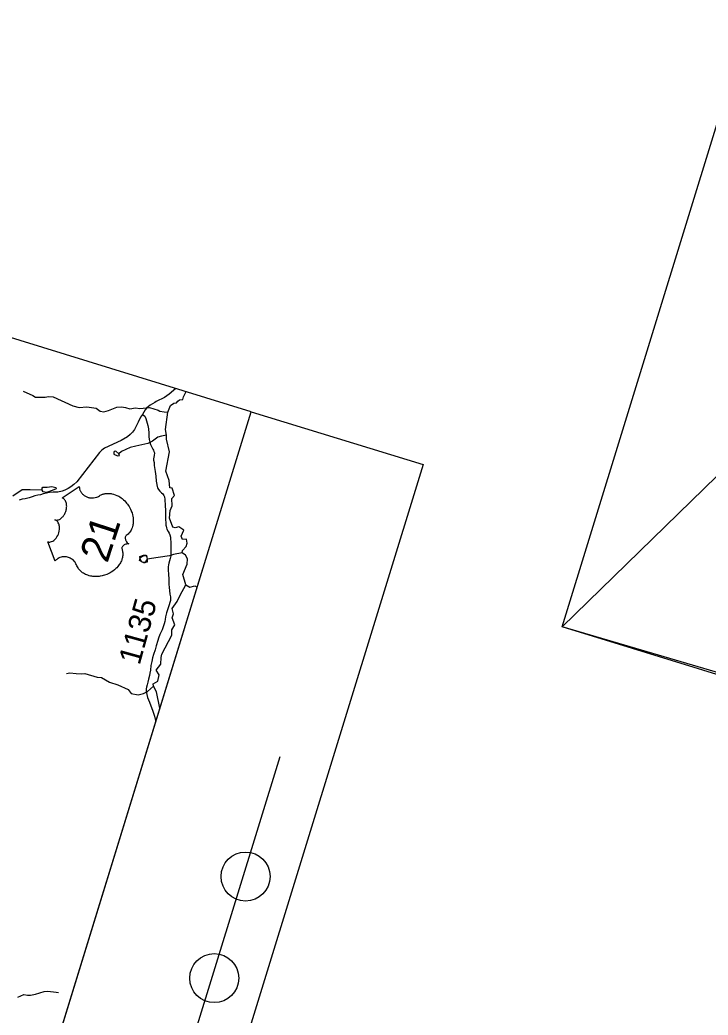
# Model space of a CAD drawing. Extents: x 1347947 to 1350662, y 1027710 to 1030532.
# Drawn here: x 1348346.4 to 1348486.3, y 1028931.2 to 1029133.4 of the extents above; entities that cross this region are included whole.
import ezdxf

# ---------------------------------------------------------------- set-up
doc = ezdxf.new("R2010")
doc.units = 0
for name, color, linetype in [('Default', 7, 'Continuous'), ('Prop Leader Line Light', 7, 'Continuous'), ('Prop Leader Line Medium', 7, 'Continuous'), ('Prop WCC CELL', 7, 'Continuous'), ('Sheet Clip Boundary CELL', 7, 'Continuous')]:
    doc.layers.add(name, color=color, linetype=linetype)

msp = doc.modelspace()

# ---------------------------------------------------------------- linework, layer by layer
at = {"layer": 'Default'}
for points in [[(1348347.12, 1029057.98), (1348349.02, 1029057.09), (1348349.61, 1029056.76), (1348351.54, 1029056.74), (1348352.24, 1029056.86), (1348353.19, 1029056.77), (1348357.15, 1029054.98), (1348358.46, 1029054.66), (1348359.99, 1029054.76), (1348361.89, 1029054.5), (1348362.71, 1029053.91), (1348363.47, 1029053.75), (1348364.41, 1029053.99), (1348366.15, 1029054.7), (1348367.05, 1029054.79), (1348367.86, 1029054.65), (1348368.73, 1029054.35), (1348369.93, 1029054.56), (1348370.79, 1029054.4), (1348372.77, 1029054.63), (1348374.51, 1029054.08), (1348374.84, 1029053.86), (1348375.76, 1029053.74), (1348376.49, 1029053.71)], [(1348378.08, 1029058.5), (1348376.76, 1029057.31), (1348375.8, 1029056.66), (1348374.14, 1029055.82), (1348373.86, 1029055.67), (1348373.35, 1029055.38), (1348372.86, 1029055.08), (1348372.24, 1029054.57), (1348371.9, 1029054.16), (1348371.32, 1029053.23)], [(1348374.86, 1028993.56), (1348374.21, 1028996.86), (1348373.6, 1028998.04), (1348373.5, 1028998.52), (1348374.42, 1028999.01), (1348374.75, 1029000.33), (1348374.14, 1029001.28), (1348375.07, 1029002.52), (1348375.11, 1029003.84), (1348375.27, 1029004.55), (1348377.29, 1029008.37), (1348377.29, 1029009.5), (1348377.91, 1029010.5), (1348377.37, 1029011.93), (1348377.66, 1029012.74), (1348377.33, 1029013.77), (1348378.37, 1029015.25), (1348378.98, 1029016.52), (1348380.12, 1029018.58), (1348379.55, 1029020.68), (1348380.44, 1029022.83), (1348380.48, 1029023.86), (1348380.05, 1029024.64), (1348379.42, 1029025.11), (1348379.49, 1029025.57), (1348380.18, 1029026.42), (1348380.4, 1029027.07), (1348380.25, 1029027.86), (1348379.47, 1029027.81), (1348379.16, 1029028.51), (1348379.73, 1029029.69), (1348378.72, 1029030.36), (1348377.96, 1029030.21), (1348377.5, 1029030.35), (1348376.8, 1029032.13), (1348376.94, 1029033.7), (1348377.34, 1029034.64), (1348377.28, 1029036.13), (1348377.83, 1029036.78), (1348377.35, 1029038.26), (1348376.91, 1029038.3), (1348376.73, 1029039.81), (1348376.08, 1029041.68), (1348376.8, 1029045.63), (1348376.18, 1029048.22), (1348376.22, 1029049.03), (1348375.99, 1029050.14), (1348376.49, 1029053.71), (1348377, 1029055.02), (1348377.69, 1029055.49), (1348378.27, 1029055.56), (1348378.48, 1029055.93), (1348378.85, 1029056.22), (1348379.53, 1029056.25), (1348379.63, 1029056.82), (1348380.18, 1029057.85)], [(1348371.32, 1029053.23), (1348370.96, 1029052.64), (1348370.43, 1029051.62), (1348370.13, 1029050.95), (1348369.68, 1029050.17), (1348369.27, 1029049.65), (1348368.85, 1029049.18), (1348368.31, 1029048.7), (1348366.99, 1029047.94), (1348363.63, 1029046.38), (1348363.08, 1029045.99), (1348362.59, 1029045.5), (1348357.97, 1029039.51), (1348357.39, 1029039.02), (1348356.77, 1029038.53), (1348356.24, 1029038.16), (1348355.96, 1029038.02), (1348355.58, 1029037.82), (1348355, 1029037.65), (1348354.15, 1029037.45), (1348353.17, 1029037.41), (1348352.46, 1029037.36), (1348351.84, 1029037.21), (1348351.18, 1029037.08), (1348350.64, 1029036.91), (1348350.1, 1029036.82), (1348349.45, 1029036.66), (1348348.9, 1029036.5), (1348348.3, 1029036.3), (1348347.5, 1029036.1), (1348346.86, 1029035.98), (1348346.29, 1029035.84)], [(1348371.32, 1029053.23), (1348371.8, 1029052.86), (1348371.98, 1029052.42), (1348372.39, 1029051), (1348372.58, 1029050.32), (1348372.63, 1029049.41), (1348372.63, 1029049.1), (1348372.65, 1029048.75), (1348372.71, 1029048.1), (1348372.83, 1029047.57), (1348372.97, 1029047.11), (1348373.15, 1029046.74), (1348373.33, 1029046.42), (1348373.46, 1029046.17), (1348373.57, 1029045.96), (1348373.65, 1029045.71), (1348373.77, 1029045.4), (1348373.73, 1029044.88), (1348373.59, 1029044.21), (1348373.6, 1029043.91), (1348373.67, 1029043.43), (1348373.71, 1029042.86), (1348373.9, 1029041.66), (1348374.06, 1029040.66), (1348374.11, 1029039.69), (1348374.18, 1029039.32), (1348374.33, 1029038.56), (1348374.39, 1029038.3), (1348374.58, 1029037.97), (1348374.85, 1029037.63), (1348375.2, 1029037.33), (1348375.45, 1029037.07), (1348375.66, 1029036.76), (1348375.77, 1029036.46), (1348375.86, 1029035.96), (1348375.92, 1029034.7), (1348376.03, 1029033.74), (1348376, 1029032.91), (1348376.03, 1029031.95), (1348376.06, 1029031.12), (1348376.08, 1029030.76), (1348376.13, 1029030.5), (1348376.18, 1029030.18), (1348376.28, 1029029.95), (1348376.53, 1029029.47), (1348376.77, 1029029.1), (1348376.86, 1029028.79), (1348376.99, 1029028.28), (1348377.02, 1029027.93), (1348377.09, 1029027.3), (1348377.09, 1029026.65), (1348377.11, 1029025.76), (1348377.09, 1029025.13), (1348377.06, 1029024.52), (1348376.93, 1029023.97), (1348376.8, 1029023.47), (1348376.68, 1029022.99), (1348376.63, 1029022.64), (1348376.58, 1029022.26), (1348376.57, 1029021.61), (1348376.59, 1029020.79), (1348376.68, 1029019.77), (1348376.66, 1029018.75), (1348376.74, 1029018.07), (1348376.83, 1029017.44), (1348376.91, 1029016.69), (1348377.01, 1029016.16), (1348377.05, 1029015.79), (1348377.01, 1029015.41), (1348376.64, 1029014.17), (1348376.42, 1029013.51), (1348376.23, 1029012.93), (1348376.03, 1029012.1), (1348375.95, 1029011.6), (1348375.84, 1029011.19), (1348375.72, 1029010.72), (1348375.3, 1029009.49), (1348374.86, 1029008.55), (1348374.61, 1029007.76), (1348374.45, 1029007.31), (1348374.1, 1029006.24), (1348373.89, 1029005.44), (1348373.56, 1029004.47), (1348373.37, 1029003.75), (1348373.22, 1029003.05), (1348373.05, 1029002.23), (1348372.93, 1029001.29), (1348372.83, 1029000.7), (1348372.73, 1029000.2), (1348372.57, 1028999.44), (1348372.42, 1028998.84), (1348372.29, 1028998.27), (1348372.12, 1028997.8), (1348372.05, 1028997.46), (1348372.05, 1028997.07), (1348372.18, 1028996.3), (1348372.37, 1028995.73), (1348372.75, 1028994.75), (1348373.42, 1028992.94), (1348373.78, 1028991.92)], [(1348376.22, 1029049.03), (1348375.22, 1029048.81), (1348374.44, 1029048.64), (1348373.37, 1029047.79), (1348372.44, 1029047.34), (1348371.21, 1029047.02), (1348369.97, 1029046.8), (1348368.81, 1029046.53), (1348367.04, 1029045.72), (1348366.53, 1029045.25)], [(1348366.53, 1029045.25), (1348365.94, 1029045.78), (1348365.6, 1029045.7), (1348365.49, 1029045.49), (1348365.5, 1029045.12), (1348366.27, 1029044.81), (1348366.63, 1029044.85), (1348366.53, 1029045.25)], [(1348366.53, 1029045.25), (1348365.94, 1029045.78), (1348365.6, 1029045.7), (1348365.49, 1029045.49), (1348365.5, 1029045.12), (1348366.27, 1029044.81), (1348366.63, 1029044.85), (1348366.53, 1029045.25)], [(1348350.95, 1029037.86), (1348348.48, 1029037.9), (1348346.88, 1029037.89), (1348344.99, 1029036.59)], [(1348350.95, 1029037.86), (1348350.93, 1029038.27), (1348351.1, 1029038.48), (1348351.98, 1029038.47), (1348352.89, 1029038.56), (1348353.69, 1029038.41), (1348353.79, 1029038.11), (1348353.01, 1029037.75), (1348351.85, 1029037.4), (1348351.16, 1029037.48), (1348350.95, 1029037.86)], [(1348379.42, 1029025.11), (1348377.63, 1029024.76), (1348376.82, 1029024.5), (1348374.54, 1029024.17), (1348372.29, 1029023.8)], [(1348372.29, 1029023.8), (1348372.3, 1029023.22), (1348371.44, 1029023.12), (1348370.74, 1029023.56), (1348370.77, 1029023.82), (1348370.95, 1029024.16), (1348371.53, 1029024.51), (1348372.12, 1029024.57), (1348372.29, 1029023.8)], [(1348371.53, 1029024.62), (1348372.1, 1029024.65), (1348372.25, 1029023.8), (1348371.84, 1029023.08), (1348371.58, 1029023.1), (1348371.23, 1029023.26), (1348370.85, 1029023.81), (1348370.76, 1029024.4), (1348371.53, 1029024.62)], [(1348380.12, 1029018.58), (1348380.97, 1029018.16), (1348381.97, 1029018.38), (1348382.43, 1029018.13)], [(1348355.92, 1029000.63), (1348356.58, 1029000.75), (1348357.84, 1029000.57), (1348358.89, 1029000.55), (1348359.59, 1029000.61), (1348362.13, 1028999.84), (1348363.03, 1028999.79), (1348364.64, 1028998.86), (1348366.33, 1028998.31), (1348368.4, 1028997.35), (1348369.03, 1028996.55), (1348370.45, 1028996.24), (1348371.53, 1028996.51), (1348372.33, 1028996.95), (1348373.6, 1028998.04)], [(1348373.78, 1028991.92), (1348373.96, 1028991.07), (1348374.02, 1028990.84)], [(1348346.01, 1028934.86), (1348347.22, 1028935.42), (1348347.98, 1028935.25), (1348348.59, 1028935.25), (1348349.59, 1028935.47), (1348351.35, 1028935.97), (1348352.13, 1028936.05), (1348353.81, 1028935.87), (1348354.24, 1028935.78)]]:
    msp.add_lwpolyline(points, dxfattribs=at)
msp.add_lwpolyline([(1348352.1, 1029027.37), (1348352.23, 1029027.33), (1348352.4, 1029027.31), (1348352.48, 1029027.31), (1348352.66, 1029027.33), (1348352.87, 1029027.39), (1348353.1, 1029027.5), (1348353.31, 1029027.64), (1348353.44, 1029027.74), (1348353.62, 1029027.91), (1348353.8, 1029028.12), (1348353.96, 1029028.36), (1348354.11, 1029028.62), (1348354.24, 1029028.91), (1348354.34, 1029029.2), (1348354.42, 1029029.53), (1348354.47, 1029029.9), (1348354.48, 1029030.08), (1348354.47, 1029030.28), (1348354.46, 1029030.47), (1348354.42, 1029030.69), (1348354.37, 1029030.87), (1348354.33, 1029031.01), (1348354.22, 1029031.23), (1348354.1, 1029031.42), (1348354.03, 1029031.5), (1348353.96, 1029031.58), (1348353.79, 1029031.7), (1348353.71, 1029031.75), (1348353.54, 1029031.82), (1348353.69, 1029031.78), (1348353.79, 1029031.77), (1348353.88, 1029031.76), (1348353.99, 1029031.77), (1348354.14, 1029031.79), (1348354.28, 1029031.83), (1348354.49, 1029031.91), (1348354.59, 1029031.97), (1348354.68, 1029032.03), (1348354.9, 1029032.2), (1348355.1, 1029032.4), (1348355.2, 1029032.51), (1348355.28, 1029032.62), (1348355.38, 1029032.76), (1348355.47, 1029032.91), (1348355.55, 1029033.06), (1348355.63, 1029033.22), (1348355.7, 1029033.39), (1348355.75, 1029033.52), (1348355.8, 1029033.69), (1348355.84, 1029033.85), (1348355.88, 1029034.02), (1348355.9, 1029034.2), (1348355.92, 1029034.36), (1348355.93, 1029034.56), (1348355.92, 1029034.75), (1348355.91, 1029034.92), (1348355.87, 1029035.14), (1348355.82, 1029035.33), (1348355.77, 1029035.47), (1348355.69, 1029035.65), (1348355.58, 1029035.83), (1348355.5, 1029035.94), (1348355.4, 1029036.03), (1348355.3, 1029036.12), (1348355.19, 1029036.19), (1348355.08, 1029036.24), (1348354.99, 1029036.27), (1348358.48, 1029038.57), (1348358.49, 1029038.49), (1348358.51, 1029038.3), (1348358.55, 1029038.14), (1348358.63, 1029037.87), (1348358.68, 1029037.75), (1348358.74, 1029037.63), (1348358.8, 1029037.52), (1348358.86, 1029037.42), (1348358.96, 1029037.29), (1348359.06, 1029037.17), (1348359.17, 1029037.04), (1348359.27, 1029036.94), (1348359.49, 1029036.77), (1348359.63, 1029036.67), (1348359.76, 1029036.6), (1348360.02, 1029036.47), (1348360.15, 1029036.42), (1348360.28, 1029036.38), (1348360.42, 1029036.34), (1348360.56, 1029036.31), (1348360.71, 1029036.29), (1348360.83, 1029036.27), (1348361, 1029036.26), (1348361.19, 1029036.26), (1348361.38, 1029036.27), (1348361.69, 1029036.33), (1348362.03, 1029036.42), (1348362.23, 1029036.5), (1348362.4, 1029036.58), (1348362.62, 1029036.72), (1348362.75, 1029036.8), (1348362.91, 1029036.88), (1348363.2, 1029037), (1348363.33, 1029037.04), (1348363.47, 1029037.08), (1348363.62, 1029037.12), (1348363.78, 1029037.15), (1348363.91, 1029037.17), (1348364.22, 1029037.19), (1348364.5, 1029037.19), (1348364.65, 1029037.18), (1348364.97, 1029037.14), (1348365.13, 1029037.11), (1348365.44, 1029037.04), (1348365.8, 1029036.92), (1348366.13, 1029036.78), (1348366.51, 1029036.59), (1348366.73, 1029036.46), (1348366.98, 1029036.29), (1348367.19, 1029036.13), (1348367.5, 1029035.87), (1348367.72, 1029035.66), (1348367.97, 1029035.4), (1348368.11, 1029035.23), (1348368.27, 1029035.03), (1348368.44, 1029034.8), (1348368.61, 1029034.53), (1348368.79, 1029034.22), (1348368.92, 1029033.97), (1348369.05, 1029033.66), (1348369.13, 1029033.47), (1348369.22, 1029033.21), (1348369.31, 1029032.86), (1348369.39, 1029032.53), (1348369.43, 1029032.25), (1348369.45, 1029032), (1348369.47, 1029031.69), (1348369.45, 1029031.19), (1348369.43, 1029031.01), (1348369.39, 1029030.81), (1348369.35, 1029030.61), (1348369.3, 1029030.43), (1348369.22, 1029030.19), (1348369.13, 1029029.95), (1348369.02, 1029029.74), (1348368.89, 1029029.52), (1348368.74, 1029029.29), (1348368.58, 1029029.1), (1348368.39, 1029028.9), (1348368.02, 1029028.6), (1348367.93, 1029028.51), (1348367.89, 1029028.45), (1348367.83, 1029028.3), (1348367.82, 1029028.15), (1348367.83, 1029027.99), (1348367.85, 1029027.89), (1348367.88, 1029027.75), (1348367.93, 1029027.64), (1348367.99, 1029027.5), (1348368.05, 1029027.4), (1348368.1, 1029027.32), (1348368.24, 1029027.16), (1348368.3, 1029027.09), (1348368.4, 1029027.02), (1348368.54, 1029026.93), (1348368.33, 1029026.95), (1348368.18, 1029026.93), (1348368.05, 1029026.9), (1348367.93, 1029026.86), (1348367.77, 1029026.8), (1348367.64, 1029026.73), (1348367.51, 1029026.64), (1348367.39, 1029026.54), (1348367.31, 1029026.46), (1348367.24, 1029026.38), (1348367.18, 1029026.28), (1348367.14, 1029026.19), (1348367.12, 1029026.11), (1348367.11, 1029026), (1348367.17, 1029025.83), (1348367.21, 1029025.66), (1348367.26, 1029025.49), (1348367.29, 1029025.29), (1348367.31, 1029025.14), (1348367.32, 1029024.97), (1348367.32, 1029024.77), (1348367.31, 1029024.57), (1348367.28, 1029024.36), (1348367.26, 1029024.18), (1348367.21, 1029023.99), (1348367.16, 1029023.82), (1348367.1, 1029023.64), (1348367.04, 1029023.48), (1348366.96, 1029023.3), (1348366.85, 1029023.08), (1348366.74, 1029022.9), (1348366.62, 1029022.71), (1348366.48, 1029022.52), (1348366.32, 1029022.32), (1348366.11, 1029022.08), (1348365.94, 1029021.91), (1348365.66, 1029021.66), (1348365.29, 1029021.38), (1348364.98, 1029021.18), (1348364.73, 1029021.04), (1348364.34, 1029020.84), (1348364.08, 1029020.73), (1348363.64, 1029020.57), (1348363.33, 1029020.48), (1348363.11, 1029020.43), (1348362.75, 1029020.36), (1348362.53, 1029020.33), (1348362.22, 1029020.3), (1348361.94, 1029020.29), (1348361.67, 1029020.29), (1348361.51, 1029020.3), (1348361.22, 1029020.33), (1348361.02, 1029020.35), (1348360.75, 1029020.4), (1348360.47, 1029020.47), (1348360.21, 1029020.55), (1348360.01, 1029020.63), (1348359.77, 1029020.73), (1348359.52, 1029020.86), (1348359.32, 1029020.98), (1348359.17, 1029021.08), (1348359, 1029021.2), (1348358.81, 1029021.36), (1348358.64, 1029021.53), (1348358.5, 1029021.69), (1348358.36, 1029021.87), (1348358.24, 1029022.04), (1348358.12, 1029022.26), (1348358.02, 1029022.47), (1348357.94, 1029022.66), (1348357.82, 1029022.9), (1348357.75, 1029023.03), (1348357.64, 1029023.19), (1348357.53, 1029023.33), (1348357.43, 1029023.44), (1348357.28, 1029023.59), (1348357.16, 1029023.69), (1348356.97, 1029023.83), (1348356.84, 1029023.92), (1348356.66, 1029024.02), (1348356.49, 1029024.1), (1348356.27, 1029024.18), (1348356.09, 1029024.23), (1348355.86, 1029024.28), (1348355.64, 1029024.31), (1348355.45, 1029024.32), (1348355.22, 1029024.31), (1348355.04, 1029024.28), (1348354.8, 1029024.23), (1348354.57, 1029024.16), (1348354.37, 1029024.07), (1348354.19, 1029023.98), (1348354.04, 1029023.88), (1348353.91, 1029023.79), (1348353.76, 1029023.66), (1348353.64, 1029023.53), (1348353.57, 1029023.45)], close=True, dxfattribs=at)
at = {"layer": 'Prop Leader Line Light'}
msp.add_line((1348356.2, 1028843.88), (1348399.28, 1028983.75), dxfattribs=at)
for centre in [(1348392.28, 1028959.36), (1348385.92, 1028938.72)]:
    msp.add_circle(centre, 4.98, dxfattribs=at)
at = {"layer": 'Prop Leader Line Medium'}
msp.add_lwpolyline([(1348456.59, 1029010.05), (1348681.97, 1029741.89), (1349133.09, 1029602.97), (1348907.71, 1028871.13)], close=True, dxfattribs=at)
at = {"layer": 'Prop WCC CELL'}
for p, q in [((1348393.41, 1029053.78), (1348175.36, 1029120.93)), ((1348285.23, 1028702.5), (1348393.41, 1029053.78))]:
    msp.add_line(p, q, dxfattribs=at)
msp.add_lwpolyline([(1348285.23, 1028702.5), (1348393.41, 1029053.78), (1348428.36, 1029043.07), (1348320.15, 1028691.84)], close=True, dxfattribs=at)
at = {"layer": 'Sheet Clip Boundary CELL'}
msp.add_lwpolyline([(1348456.59, 1029010.05), (1348582.47, 1029132.61), (1348611.5, 1029255.07), (1348756.63, 1029710.8), (1349133.09, 1029602.97), (1349132.8, 1029579.86), (1349058.53, 1029368.75), (1348907.71, 1028871.13), (1348666.12, 1028948.43)], close=True, dxfattribs=at)

# ---------------------------------------------------------------- texts
at = {"layer": 'Default'}
msp.add_text('21', height=6.002, rotation=71.9667, dxfattribs=at).set_placement((1348364.19, 1029022.87))
at = {"layer": 'Prop Leader Line Light'}
msp.add_text('1135', height=4.5, rotation=74.558, dxfattribs=at).set_placement((1348370.74, 1029002.15))

doc.saveas('drawing.dxf')
